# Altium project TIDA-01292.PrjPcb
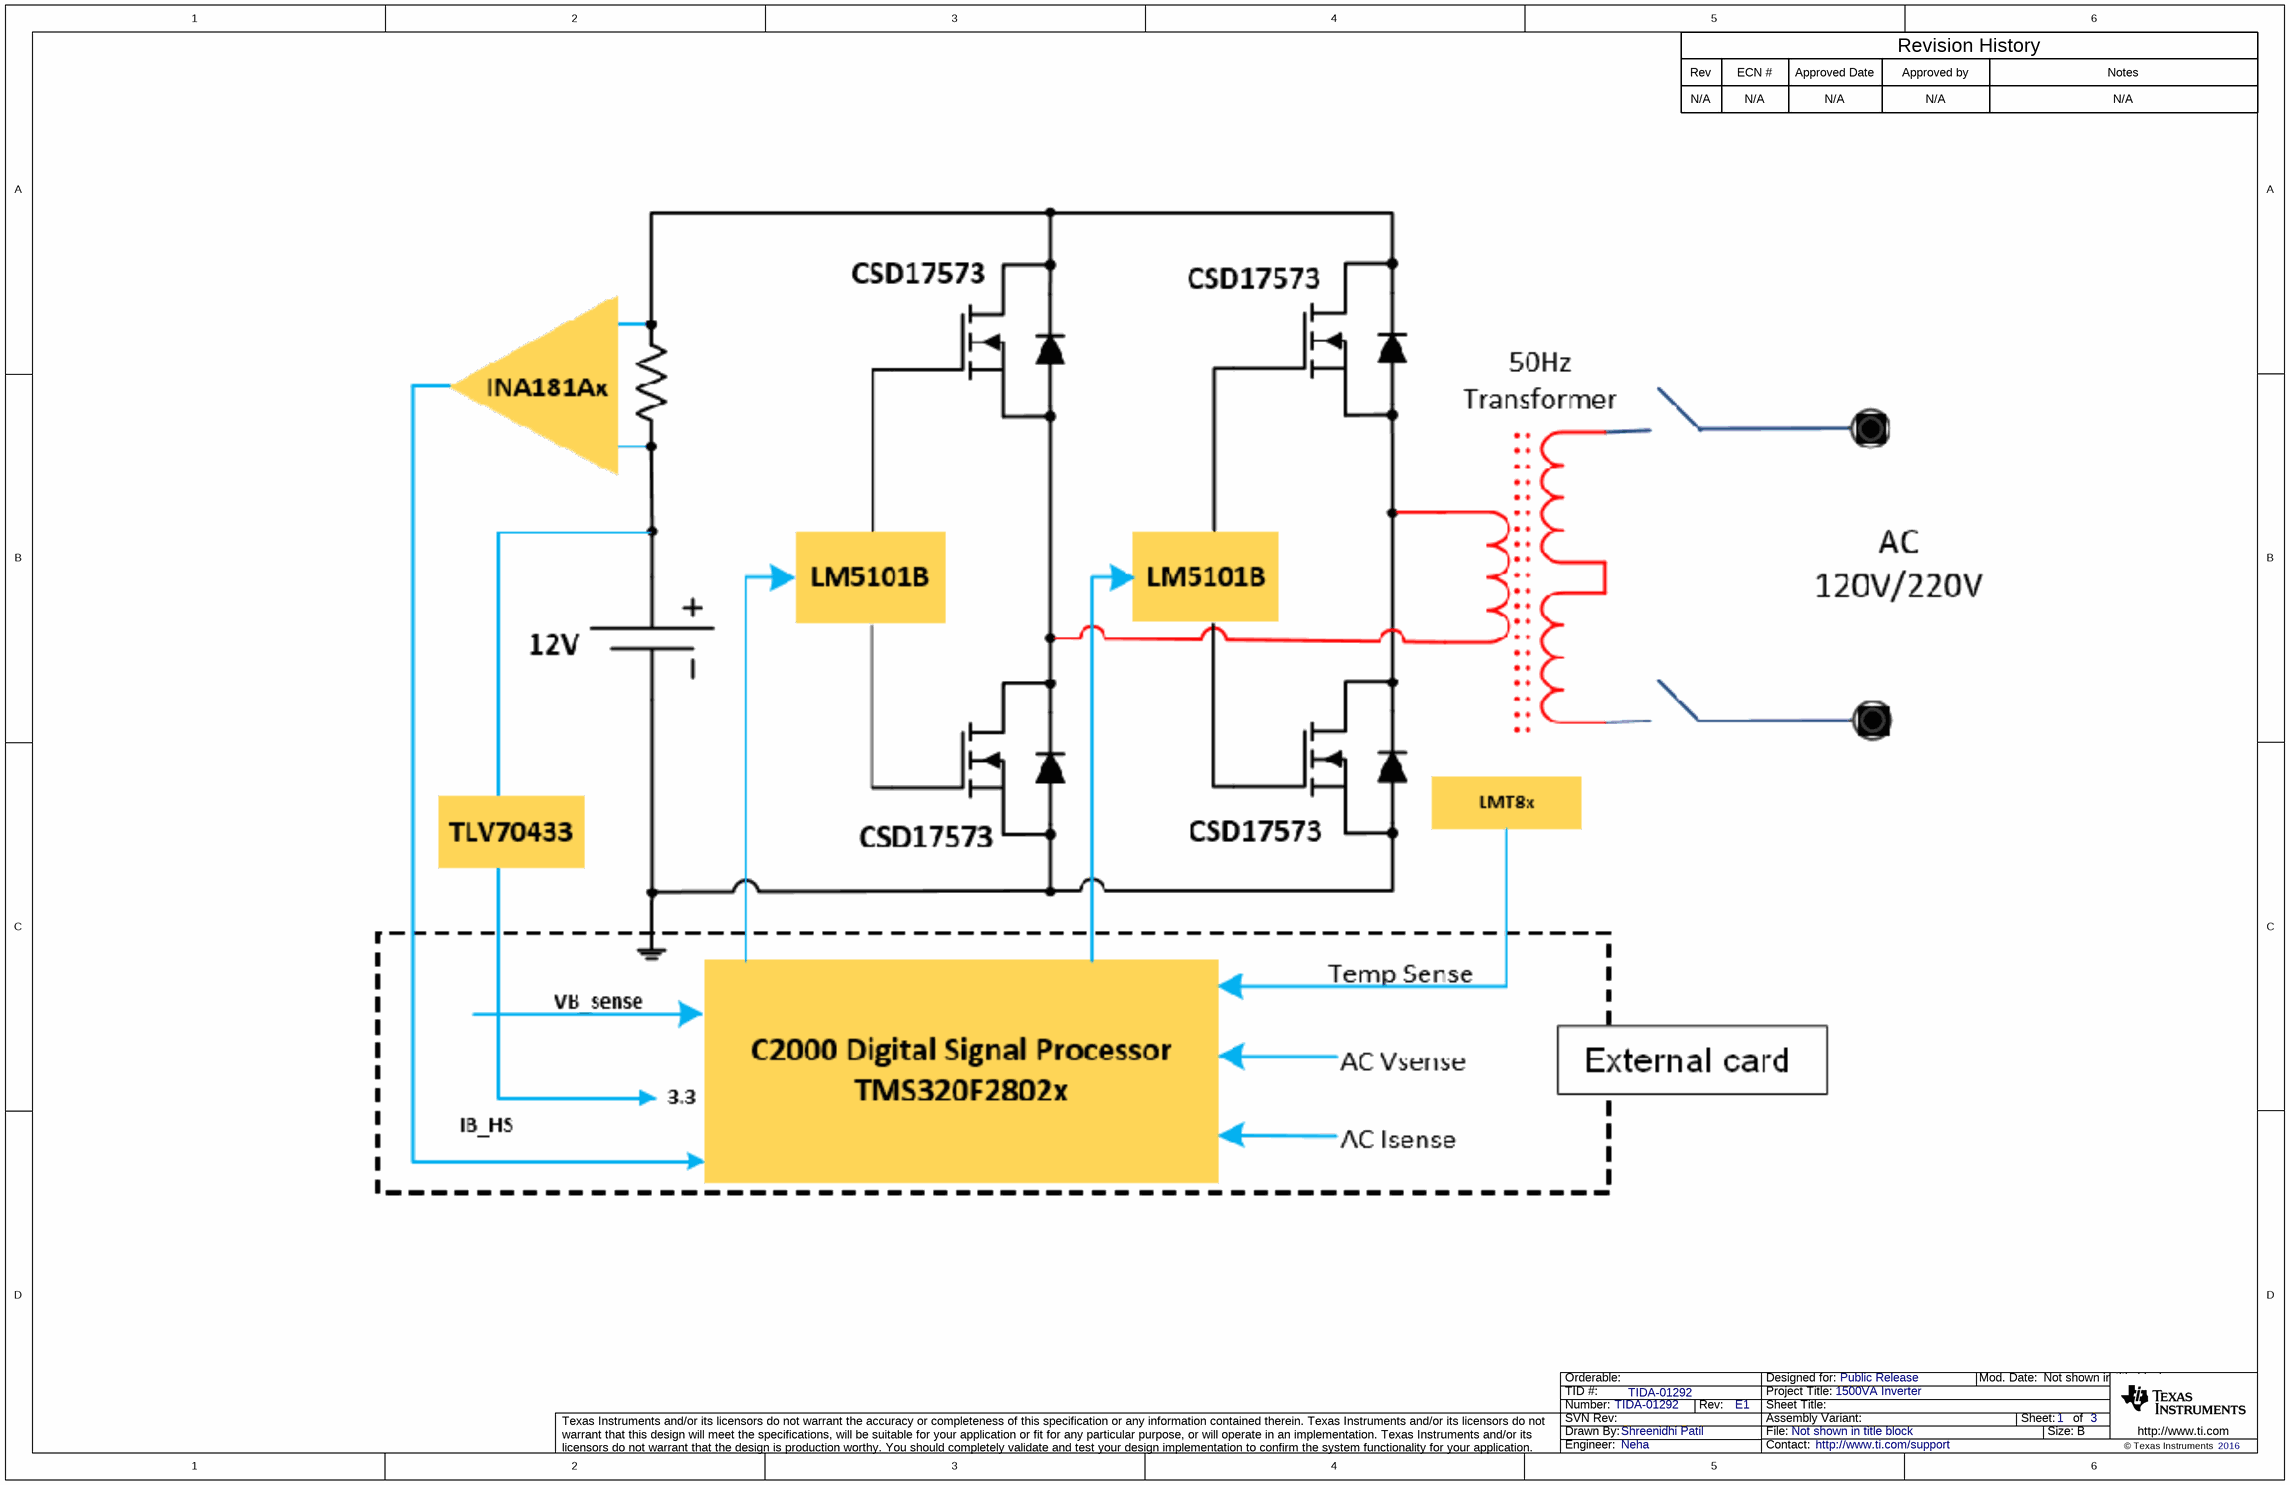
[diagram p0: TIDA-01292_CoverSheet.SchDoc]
CopyrightYear: 2016; PCB_Layout: Manjunath M; PCB_Rev: E1; PRJ_Customer: Public Release; PRJ_Engineer: Neha; PRJ_Number: TIDA-01292; PRJ_Title: 1500VA Inverter; SCH_Rev: E1; TechSupport: http://www.ti.com/support; TID: TIDA-01292
3 sheets, 119 parts. Net scope: global (net labels, ports and power ports of the same name join across sheets).
Board file: TIDA-01292.PcbDoc
Sheets:
  TIDA-01292_CoverSheet.SchDoc
  TIDA-01292_Sheet1.SchDoc
  TIDA-01292_EVM_Hardware.SchDoc

## Sheet TIDA-01292_CoverSheet.SchDoc
size 431 x 279 mm; Date: Not shown in title block; ApprovedBy: Not shown in title block; CheckedBy: Not shown in title block; Author: Not shown in title block; CompanyName: Not shown in title block; DrawnBy: Shreenidhi Patil; Engineer: Not shown in title block; Organization: Not shown in title block; Address1: Not shown in title block; Address2: Not shown in title block; Address3: Not shown in title block; Address4: Not shown in title block; DocumentNumber: 1; Revision: Use project parameter SCH_Rev; SheetNumber: 1; SheetTotal: 3; PageSetup: Record=PageOptions¦CenterHorizontal=True¦CenterVertical=True¦PrintScale=1.00¦XCorrection=1.00¦YCorrection=1.00¦PrintKind=0¦BorderSize=5000000¦LeftOffset=0¦BottomOffset=0¦Orientation=2¦PaperLength=1000¦PaperWidth=1000¦Scale=100¦PaperSource=15¦PrintQuality=600¦MediaType=1¦DitherType=10¦PaperKind=Letter¦PrintScaleMode=1

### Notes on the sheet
- Rev
- N/A
- ECN #
- Approved Date
- Approved by
- Revision History
- Notes

## Sheet TIDA-01292_Sheet1.SchDoc
size 431 x 279 mm; Date: Not shown in title block; ApprovedBy: Not shown in title block; CheckedBy: Not shown in title block; Author: Not shown in title block; CompanyName: Not shown in title block; DrawnBy: Shreenidhi Patil; Engineer: Not shown in title block; Organization: Not shown in title block; Address1: Not shown in title block; Address2: Not shown in title block; Address3: Not shown in title block; Address4: Not shown in title block; DocumentNumber: 1; Revision: Use project parameter SCH_Rev; SheetNumber: 2; SheetTotal: 3; PageSetup: Record=PageOptions¦CenterHorizontal=True¦CenterVertical=True¦PrintScale=1.00¦XCorrection=1.00¦YCorrection=1.00¦PrintKind=0¦BorderSize=5000000¦LeftOffset=0¦BottomOffset=0¦Orientation=2¦PaperLength=1000¦PaperWidth=1000¦Scale=100¦PaperSource=15¦PrintQuality=600¦MediaType=1¦DitherType=10¦PaperKind=Letter¦PrintScaleMode=1
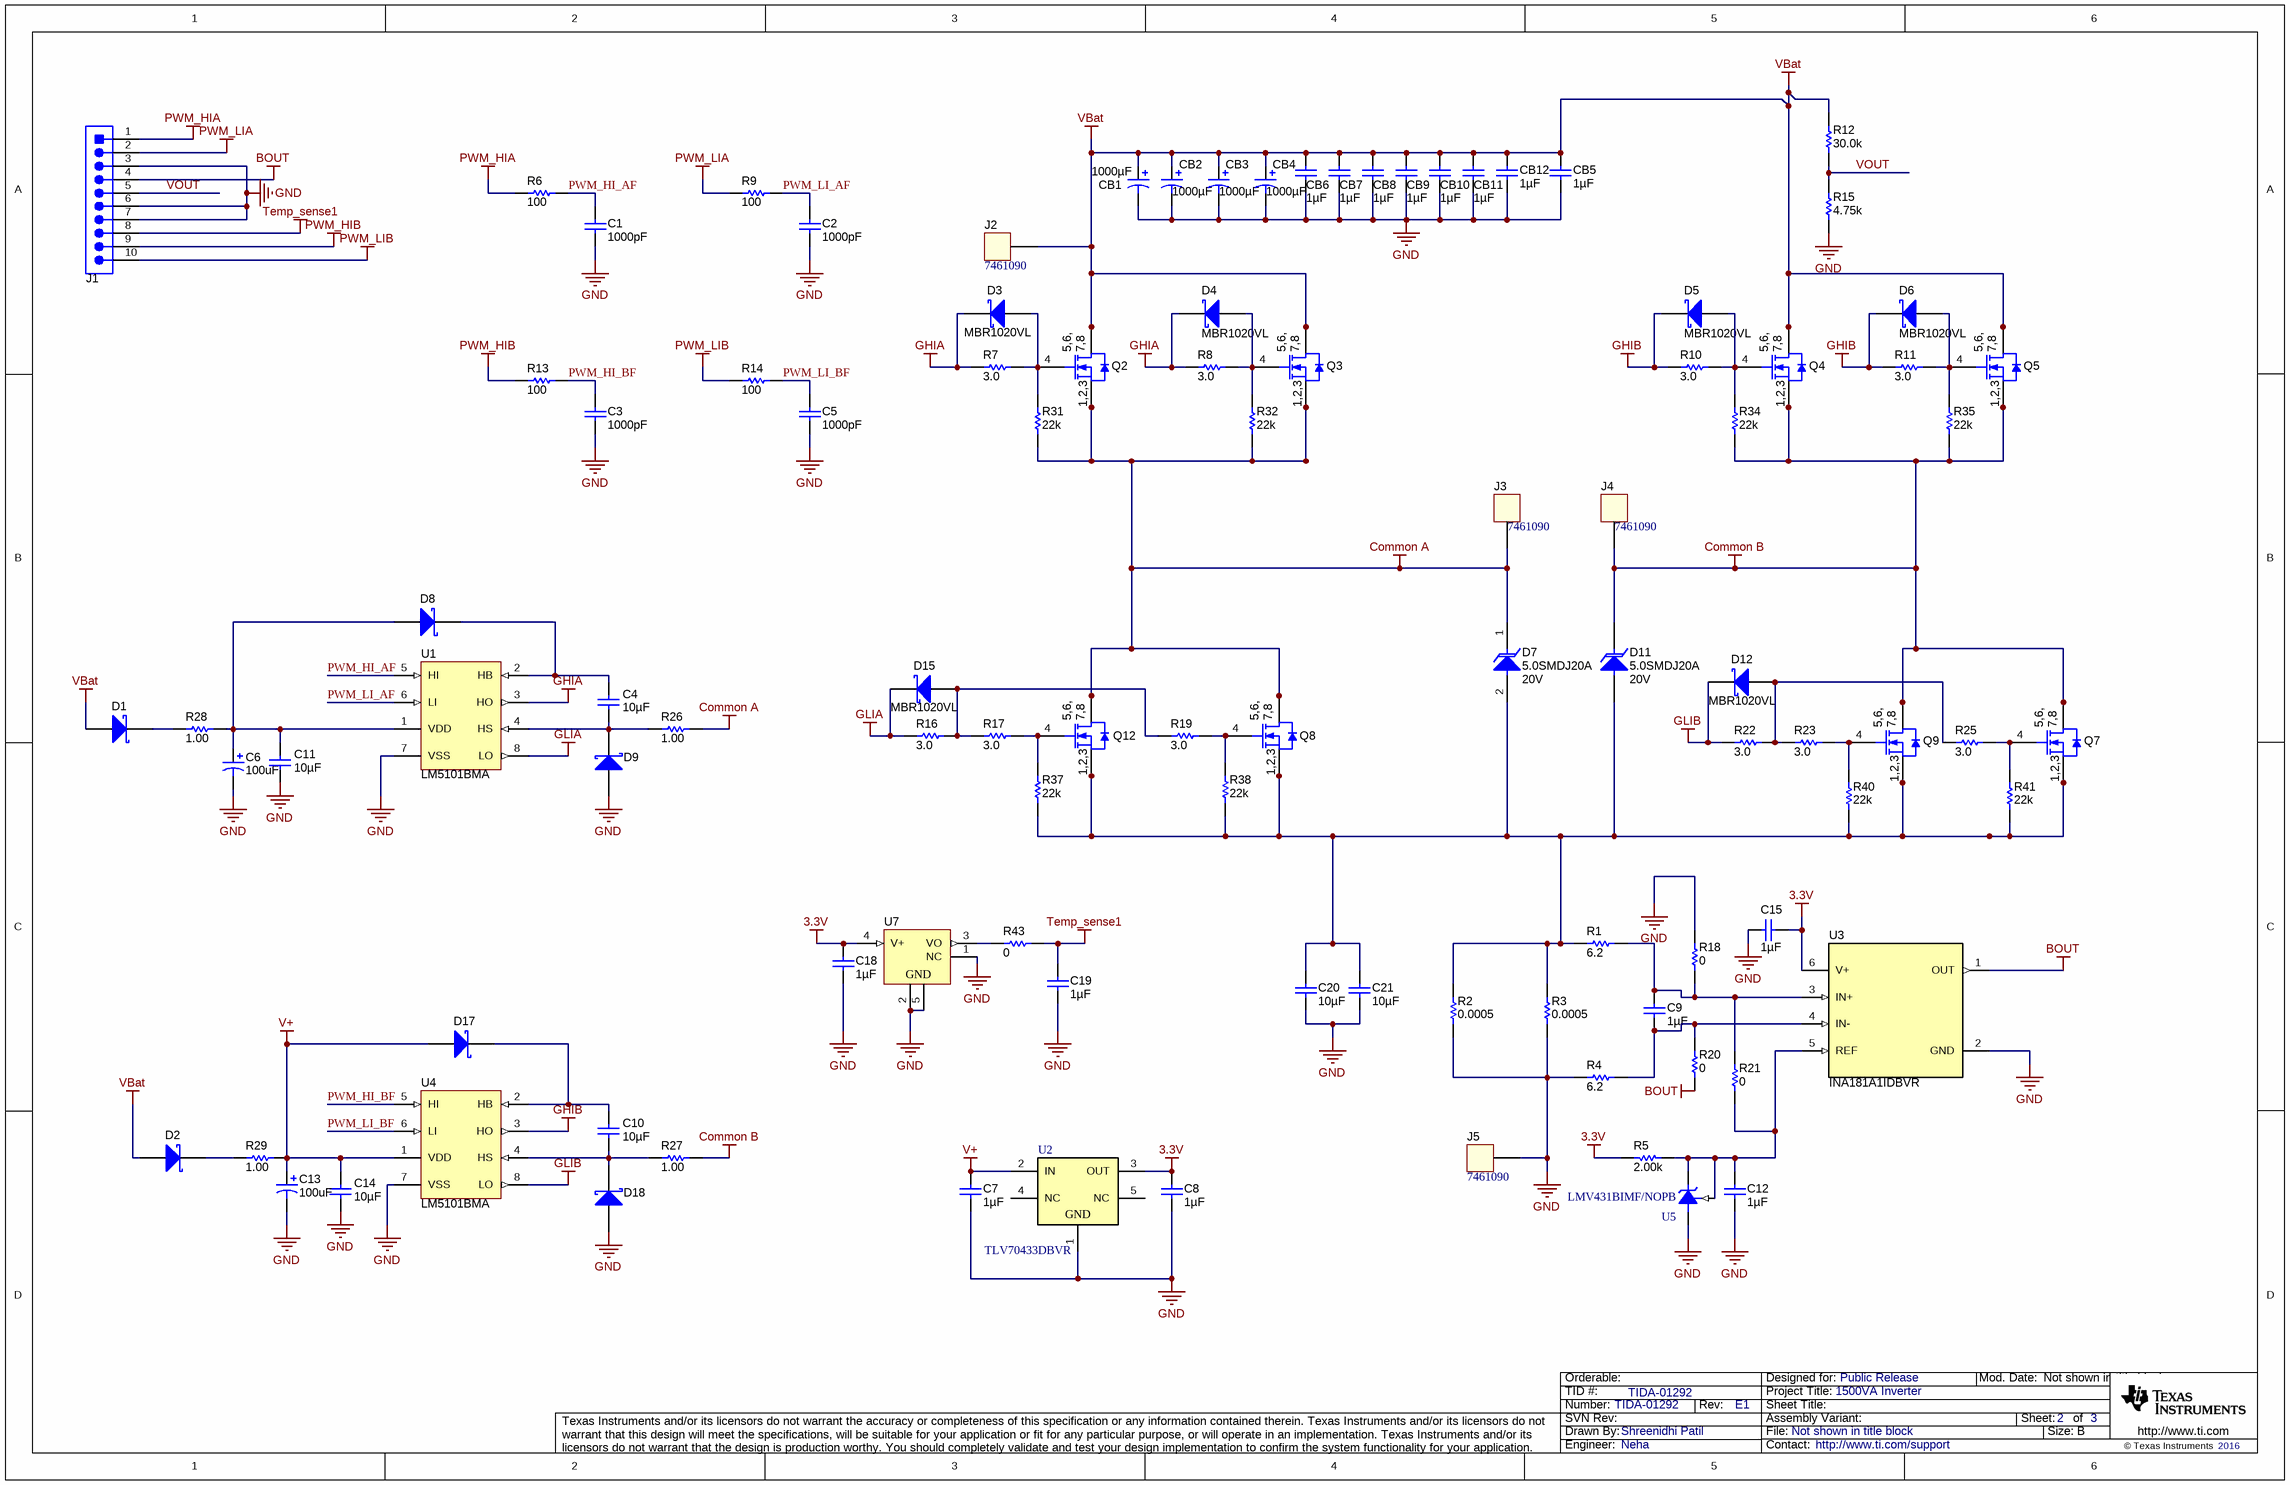
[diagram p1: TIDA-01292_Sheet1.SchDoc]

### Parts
C1  ValueDisplayed: 1000pF  [0603]  (hidden comment: 885012206034)
C2  ValueDisplayed: 1000pF  [0603]  (hidden comment: 885012206034)
C3  ValueDisplayed: 1000pF  [0603]  (hidden comment: 885012206034)
C4  ValueDisplayed: 10µF  [1206_180]  (hidden comment: C3216X5R1H106K160AB)
C5  ValueDisplayed: 1000pF  [0603]  (hidden comment: 885012206034)
C6  ValueDisplayed: 100uF  [ZLH_1000x2300]  (hidden comment: 860130475005)
C7  ValueDisplayed: 1µF  [0603]  (hidden comment: C0603C105K3RACTU)
C8  ValueDisplayed: 1µF  [0603]  (hidden comment: C0603C105K3RACTU)
C9  ValueDisplayed: 1µF  [0603]  (hidden comment: C0603C105K3RACTU)
C10  ValueDisplayed: 10µF  [1206_180]  (hidden comment: C3216X5R1H106K160AB)
C11  ValueDisplayed: 10µF  [1206_180]  (hidden comment: C3216X5R1H106K160AB)
C12  ValueDisplayed: 1µF  [0603]  (hidden comment: C0603C105K3RACTU)
C13  ValueDisplayed: 100uF  [ZLH_1000x2300]  (hidden comment: 860130475005)
C14  ValueDisplayed: 10µF  [1206_180]  (hidden comment: C3216X5R1H106K160AB)
C15  ValueDisplayed: 1µF  [0603]  (hidden comment: C0603C105K3RACTU)
C18  ValueDisplayed: 1µF  [0603]  (hidden comment: C0603C105K3RACTU)
C19  ValueDisplayed: 1µF  [0603]  (hidden comment: C0603C105K3RACTU)
C20  ValueDisplayed: 10µF  [1210_280]  (hidden comment: 1210YD106KAT2A)
C21  ValueDisplayed: 10µF  [1210_280]  (hidden comment: 1210YD106KAT2A)
CB1  ValueDisplayed: 1000µF  [ZLH_1000x2300]  (hidden comment: 25ZLH1000MEFC10X23)
CB2  ValueDisplayed: 1000µF  [ZLH_1000x2300]  (hidden comment: 25ZLH1000MEFC10X23)
CB3  ValueDisplayed: 1000µF  [ZLH_1000x2300]  (hidden comment: 25ZLH1000MEFC10X23)
CB4  ValueDisplayed: 1000µF  [ZLH_1000x2300]  (hidden comment: 25ZLH1000MEFC10X23)
CB5  ValueDisplayed: 1µF  [1206]  (hidden comment: 12063C105KAT2A)
CB6  ValueDisplayed: 1µF  [1206]  (hidden comment: 12063C105KAT2A)
CB7  ValueDisplayed: 1µF  [1206]  (hidden comment: 12063C105KAT2A)
CB8  ValueDisplayed: 1µF  [1206]  (hidden comment: 12063C105KAT2A)
CB9  ValueDisplayed: 1µF  [1206]  (hidden comment: 12063C105KAT2A)
CB10  ValueDisplayed: 1µF  [1206]  (hidden comment: 12063C105KAT2A)
CB11  ValueDisplayed: 1µF  [1206]  (hidden comment: 12063C105KAT2A)
CB12  ValueDisplayed: 1µF  [1206]  (hidden comment: 12063C105KAT2A)
D1  MBR1020VL  [SOD-123F]  (value not drawn)
D2  MBR1020VL  [SOD-123F]  (value not drawn)
D3  MBR1020VL  [SOD-123F]
D4  MBR1020VL  [SOD-123F]
D5  MBR1020VL  [SOD-123F]
D6  MBR1020VL  [SOD-123F]
D7  5.0SMDJ20A  value 20V  [SMC]
D8  MBR1020VL  [SOD-123F]  (value not drawn)
D9  MBR1020VL  [SOD-123F]  (value not drawn)
D11  5.0SMDJ20A  value 20V  [SMC]
D12  MBR1020VL  [SOD-123F]
D15  MBR1020VL  [SOD-123F]
D17  MBR1020VL  [SOD-123F]  (value not drawn)
D18  MBR1020VL  [SOD-123F]  (value not drawn)
J1  TSW-110-07-G-S  [TSW-110-07-G-S]  (value not drawn)
J2  7461090  [7461090_Chemical Surface]
J3  7461090  [7461090_Chemical Surface]
J4  7461090  [7461090_Chemical Surface]
J5  7461090  [7461090_Chemical Surface]
Q2  CSD17573Q5B  [TRANS_NexFET_Q5B]  (value not drawn)
Q3  CSD17573Q5B  [TRANS_NexFET_Q5B]  (value not drawn)
Q4  CSD17573Q5B  [TRANS_NexFET_Q5B]  (value not drawn)
Q5  CSD17573Q5B  [TRANS_NexFET_Q5B]  (value not drawn)
Q7  CSD17573Q5B  [TRANS_NexFET_Q5B]  (value not drawn)
Q8  CSD17573Q5B  [TRANS_NexFET_Q5B]  (value not drawn)
Q9  CSD17573Q5B  [TRANS_NexFET_Q5B]  (value not drawn)
Q12  CSD17573Q5B  [TRANS_NexFET_Q5B]  (value not drawn)
R1  ValueDisplayed: 6.2  [0603]  (hidden comment: CRCW06036R20JNEA)
R2  ValueDisplayed: 0.0005  [CSS2725_0005]  (hidden comment: CSS2725FTL500)
R3  ValueDisplayed: 0.0005  [CSS2725_0005]  (hidden comment: CSS2725FTL500)
R4  ValueDisplayed: 6.2  [0603]  (hidden comment: CRCW06036R20JNEA)
R5  ValueDisplayed: 2.00k  [0603]  (hidden comment: CRCW06032K00FKEA)
R6  ValueDisplayed: 100  [0603]  (hidden comment: CRCW0603100RFKEA)
R7  ValueDisplayed: 3.0  [1206]  (hidden comment: CRCW12063R00JNEA)
R8  ValueDisplayed: 3.0  [1206]  (hidden comment: CRCW12063R00JNEA)
R9  ValueDisplayed: 100  [0603]  (hidden comment: CRCW0603100RFKEA)
R10  ValueDisplayed: 3.0  [1206]  (hidden comment: CRCW12063R00JNEA)
R11  ValueDisplayed: 3.0  [1206]  (hidden comment: CRCW12063R00JNEA)
R12  ValueDisplayed: 30.0k  [0603]  (hidden comment: RC0603FR-0730KL)
R13  ValueDisplayed: 100  [0603]  (hidden comment: CRCW0603100RFKEA)
R14  ValueDisplayed: 100  [0603]  (hidden comment: CRCW0603100RFKEA)
R15  ValueDisplayed: 4.75k  [0603]  (hidden comment: RC0603FR-074K75L)
R16  ValueDisplayed: 3.0  [1206]  (hidden comment: CRCW12063R00JNEA)
R17  ValueDisplayed: 3.0  [1206]  (hidden comment: CRCW12063R00JNEA)
R18  ValueDisplayed: 0  [0603]  (hidden comment: RC0603JR-070RL)
R19  ValueDisplayed: 3.0  [1206]  (hidden comment: CRCW12063R00JNEA)
R20  ValueDisplayed: 0  [0603]  (hidden comment: RC0603JR-070RL)
R21  ValueDisplayed: 0  [0603]  (hidden comment: RC0603JR-070RL)
R22  ValueDisplayed: 3.0  [1206]  (hidden comment: CRCW12063R00JNEA)
R23  ValueDisplayed: 3.0  [1206]  (hidden comment: CRCW12063R00JNEA)
R25  ValueDisplayed: 3.0  [1206]  (hidden comment: CRCW12063R00JNEA)
R26  ValueDisplayed: 1.00  [1206]  (hidden comment: RC1206FR-071RL)
R27  ValueDisplayed: 1.00  [1206]  (hidden comment: RC1206FR-071RL)
R28  ValueDisplayed: 1.00  [1206]  (hidden comment: CSR1206FK1R00)
R29  ValueDisplayed: 1.00  [1206]  (hidden comment: CSR1206FK1R00)
R31  ValueDisplayed: 22k  [0603]  (hidden comment: CRCW060322K0JNEA)
R32  ValueDisplayed: 22k  [0603]  (hidden comment: CRCW060322K0JNEA)
R34  ValueDisplayed: 22k  [0603]  (hidden comment: CRCW060322K0JNEA)
R35  ValueDisplayed: 22k  [0603]  (hidden comment: CRCW060322K0JNEA)
R37  ValueDisplayed: 22k  [0603]  (hidden comment: CRCW060322K0JNEA)
R38  ValueDisplayed: 22k  [0603]  (hidden comment: CRCW060322K0JNEA)
R40  ValueDisplayed: 22k  [0603]  (hidden comment: CRCW060322K0JNEA)
R41  ValueDisplayed: 22k  [0603]  (hidden comment: CRCW060322K0JNEA)
R43  ValueDisplayed: 0  [0603]  (hidden comment: CRCW06030000Z0EA)
U1  LM5101BMA  [M08A_N]
U2  TLV70433DBVR  [DBV0005A_N]
U3  INA181A1IDBVR  [DBV0006A_N]
U4  LM5101BMA  [M08A_N]
U5  LMV431BIMF/NOPB  [MF03A_N]
U7  LM20CIM7X  [MAA05A_N]  (value not drawn)

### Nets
3.3V: C8.1 C15.1 C18.1 R5.2 U2.3(OUT) U3.6(V+) U7.4(V+)
BOUT: J1.4 R20.1 U3.1(OUT)
Common A: D7.1(K) J3.1 Q2.1(S) Q2.2(S) Q2.3(S) Q3.1(S) Q3.2(S) Q3.3(S) Q8.5(D) Q8.6(D) Q8.7(D) Q8.8(D) Q12.5(D) Q12.6(D) Q12.7(D) Q12.8(D) R26.2 R31.1 R32.1
Common B: D11.1(K) J4.1 Q4.1(S) Q4.2(S) Q4.3(S) Q5.1(S) Q5.2(S) Q5.3(S) Q7.5(D) Q7.6(D) Q7.7(D) Q7.8(D) Q9.5(D) Q9.6(D) Q9.7(D) Q9.8(D) R27.2 R34.1 R35.1
GHIA: D3.1(K) D4.1(K) R7.1 R8.1 U1.3(HO)
GHIB: D5.1(K) D6.1(K) R10.1 R11.1 U4.3(HO)
GLIA: D15.1(K) R16.1 U1.8(LO)
GLIB: D12.1(K) R22.1 U4.8(LO)
GND: C1.2 C2.2 C3.2 C5.2 C6.2(-) C7.2 C8.2 C11.2 C12.2 C13.2(-) C14.2 C15.2 C18.2 C19.2 C20.2 C21.2 CB1.2(-) CB2.2(-) CB3.2(-) CB4.2(-) CB5.2 CB6.2 CB7.2 CB8.2 CB9.2 CB10.2 CB11.2 CB12.2 D9.2(A) D18.2(A) J1.3 J1.6 J1.7 J5.1 R2.1 R3.1 R4.1 R15.1 R18.2 U1.7(VSS) U2.1(GND) U3.2(GND) U4.7(VSS) U5.3(A) U7.1(NC) U7.2(GND) U7.5(GND)
PWM_HIA: J1.1 R6.1
PWM_HIB: J1.9 R13.1
PWM_LIA: J1.2 R9.1
PWM_LIB: J1.10 R14.1
Temp_sense1: C19.1 J1.8 R43.2
V+: C7.1 C13.1(+) C14.1 D17.2(A) R29.2 U2.2(IN) U4.1(VDD)
VBat: CB1.1(+) CB2.1(+) CB3.1(+) CB4.1(+) CB5.1 CB6.1 CB7.1 CB8.1 CB9.1 CB10.1 CB11.1 CB12.1 D1.2(A) D2.2(A) J2.1 Q2.5(D) Q2.6(D) Q2.7(D) Q2.8(D) Q3.5(D) Q3.6(D) Q3.7(D) Q3.8(D) Q4.5(D) Q4.6(D) Q4.7(D) Q4.8(D) Q5.5(D) Q5.6(D) Q5.7(D) Q5.8(D) R12.2
PWM_HI_AF: C1.1 R6.2 U1.5(HI)
PWM_HI_BF: C3.1 R13.2 U4.5(HI)
PWM_LI_AF: C2.1 R9.2 U1.6(LI)
PWM_LI_BF: C5.1 R14.2 U4.6(LI)
VOUT: J1.5 R12.1 R15.2
NetC4_1: C4.1 D8.1(K) U1.2(HB)
NetC4_2: C4.2 D9.1(K) R26.1 U1.4(HS)
NetC6_1: C6.1(+) C11.1 D8.2(A) R28.2 U1.1(VDD)
NetC9_1: C9.1 R1.2 R18.1 R21.2 U3.3(IN+)
NetC9_2: C9.2 R4.2 R20.2 U3.4(IN-)
NetC10_1: C10.1 D17.1(K) U4.2(HB)
NetC10_2: C10.2 D18.1(K) R27.1 U4.4(HS)
NetC12_1: C12.1 R5.1 R21.1 U3.5(REF) U5.1(REF) U5.2(K)
NetC20_1: C20.1 C21.1 D7.2(A) D11.2(A) Q7.1(S) Q7.2(S) Q7.3(S) Q8.1(S) Q8.2(S) Q8.3(S) Q9.1(S) Q9.2(S) Q9.3(S) Q12.1(S) Q12.2(S) Q12.3(S) R1.1 R2.2 R3.2 R37.1 R38.1 R40.1 R41.1
NetD1_1: D1.1(K) R28.1
NetD2_1: D2.1(K) R29.1
NetD3_2: D3.2(A) Q2.4(G) R7.2 R31.2
NetD4_2: D4.2(A) Q3.4(G) R8.2 R32.2
NetD5_2: D5.2(A) Q4.4(G) R10.2 R34.2
NetD6_2: D6.2(A) Q5.4(G) R11.2 R35.2
NetD12_2: D12.2(A) R22.2 R23.1 R25.1
NetD15_2: D15.2(A) R16.2 R17.1 R19.1
NetQ7_4: Q7.4(G) R25.2 R41.2
NetQ8_4: Q8.4(G) R19.2 R38.2
NetQ9_4: Q9.4(G) R23.2 R40.2
NetQ12_4: Q12.4(G) R17.2 R37.2
NetR43_1: R43.1 U7.3(VO)

Not connected (* = marked no-connect by the designer): U2 4(NC) 5(NC)

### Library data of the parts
C1-C3 C5 = 885012206034: CAP, CERM, 1000 pF, 16 V, +/- 10%, X7R, 0603; Manufacturer: Wurth Elektronik; Polarized: N; CompType: Capacitor; Value: 1000pF; U/M: EA; Cap_F: 0.000000001; Tolerance_%: 10; Value1: Unknown; VDC_V: 16; Value2: 16V; TaMin_C: -55; TaMax_C: 125; SizeArea_mm2: 1.28; SizeAreaWB_mm2: 4.68; SizeX_mm: 1.6; SizeY_mm: 0.8; SizeZ_mm: 1; AEC Category: Q200
C4 C10 C11 C14 = C3216X5R1H106K160AB: CAP, CERM, 10 µF, 50 V, +/- 10%, X5R, 1206; Manufacturer: TDK; Polarized: N; CompType: Capacitor; Value: 10uF; U/M: EA; Cap_F: 0.00001; Tolerance_%: 10; Value1: 0.002229 ohm; VDC_V: 50; Value2: 50V; ESR_ohm: 0.002229; IRMS_A: 4.85932; TaMin_C: -55; TaMax_C: 85; SizeAreaWB_mm2: 10.92; SizeArea_mm2: 5.12; SizeX_mm: 3.2; SizeY_mm: 1.6; SizeZ_mm: 1.8; AEC Category: Q200
C6 C13 = 25ZLH1000MEFC10X23: CAP ALUM 100UF 20% 25V RADIAL; Manufacturer: Rubycon; Polarized: Y; CompType: Capacitor; U/M: EA; Cap_F: 0.001; Tolerance_%: 20; Value1: 0.018 ohm; VDC_V: 25; ESR_ohm: 0.018; IRMS_A: 2.25; TaMin_C: -40; TaMax_C: 105; Cap_Case: 10x23mm; AEC Category: Q200
C7-C9 C12 C15 C18 C19 = C0603C105K3RACTU: CAP, CERM, 1 µF, 25 V, +/- 10%, X7R, 0603; Manufacturer: Kemet; Polarized: N; CompType: Capacitor; Value: 1uF; U/M: EA; Cap_F: 0.000001; Tolerance_%: 10; Value1: Unknown; VDC_V: 25; Value2: 25V; TaMin_C: -55; TaMax_C: 125; SizeArea_mm2: 1.28; SizeAreaWB_mm2: 4.68; SizeX_mm: 1.6; SizeY_mm: 0.8; SizeZ_mm: 1; AEC Category: Q200
C20 C21 = 1210YD106KAT2A: CAP, CERM, 10 µF, 16 V, +/- 10%, X5R, 1210; Manufacturer: AVX; Polarized: N; CompType: Capacitor; Value: 10uF; U/M: EA; Cap_F: 0.00001; Tolerance_%: 10; Value1: Unknown; VDC_V: 16; Value2: 16V; TaMin_C: -55; TaMax_C: 85; Cap_Case: 1210; SizeArea_mm2: 8; SizeAreaWB_mm2: 14.7; SizeX_mm: 3.2; SizeY_mm: 2.5; SizeZ_mm: 2.8; AEC Category: Q200
CB1-CB4 = 25ZLH1000MEFC10X23: CAP, AL, 1000 µF, 25 V, +/- 20%, 0.018 ohm, TH; Manufacturer: Rubycon; Polarized: Y; CompType: Capacitor; Value: 1000uF; U/M: EA; Cap_F: 0.001; Tolerance_%: 20; VDC_V: 25; Value2: 25V; ESR_ohm: 0.018; IRMS_A: 2.25; TaMin_C: -40; TaMax_C: 105; Cap_Case: 10x23mm; AEC Category: Q200
CB5-CB12 = 12063C105KAT2A: CAP, CERM, 1 µF, 25 V, +/- 10%, X7R, 1206; Manufacturer: AVX; Polarized: N; CompType: Capacitor; Value: 1uF; U/M: EA; Cap_F: 0.000001; Tolerance_%: 10; ESR_ohm: 0.013; Value1: 0.013 ohm; VDC_V: 25; Value2: 25V; TaMin_C: -55; TaMax_C: 125; SizeArea_mm2: 5.12; SizeAreaWB_mm2: 10.92; SizeX_mm: 3.2; SizeY_mm: 1.6; SizeZ_mm: 1.35; AEC Category: Q200
D1-D6 D8 D9 D12 D15 D17 D18 = MBR1020VL: Diode, Schottky, 20 V, 1 A, SOD-123F; Manufacturer: Fairchild Semiconductor; U/M: EA; Vf_V: 0.34; Value: 20V; Value1: 1A; Value2: 0.34V; Io_A: 1; Vr_V: 20; TJmax_C: 125; SizeAreaWB_mm2: 11.7; SizeArea_mm2: 5.6; SizeX_mm: 3.5; SizeY_mm: 1.6; SizeZ_mm: 1.1; AEC Category: Q101; AEC Qualified: N
D7 D11 = 5.0SMDJ20A: Diode, TVS, Uni, 20 V, 5000 W, SMC; Manufacturer: Littelfuse; U/M: EA; Power_W: 6.5; Vr_V: 20; Value1: 6.5W; RJA_CperW: 75; SizeAreaWB_mm2: 83.2686; SizeArea_mm2: 50.5686; SizeX_mm: 8.13; SizeY_mm: 6.22; SizeZ_mm: 2.6; AEC Category: Q101
J1 = TSW-110-07-G-S: Header, 100mil, 10x1, Gold, TH; Manufacturer: Samtec; SymbolCreator: a0412235; Pitch_mm: 2.54; Gender: Male; Shrouded: N; Row_Count: 1; Current_A: 6.3; Voltage_V: 550; Cert_CSA: Y
J2-J5 = 7461090: REDCUBE PRESS-FIT with internal thread, circumference WP-BUCF, M8, 13.5 mm; Pin Number: 20; Rated Current: 340 A; Thread Length: 13.5 mm
Q2-Q5 Q7-Q9 Q12 = CSD17573Q5B: MOSFET, N-CH, 30 V, 100 A, SON 5x6mm; Manufacturer: Texas Instruments; Alternate Manufacturer: None; U/M: EA; ChType: N; Value: 30V; VdsMax_V: 30; Value1: 0.00145 ohm; Rdson45_ohm: 0.00145; Value2: 49 nC; QgTyp_nC: 49; Vgs_V: 20; IdsMax_A: 100; SizeAreaWB_mm2: 57.51; SizeArea_mm2: 31.11; SizeX_mm: 6.1; SizeY_mm: 5.1; SizeZ_mm: 1.05; AEC Category: Q101
R1 R4 = CRCW06036R20JNEA: RES, 6.2, 5%, 0.1 W, 0603; Manufacturer: Vishay-Dale; CompType: Resistor; Value: 6.2; Value_Code: 6R20; Tolerance_%: 5; Power_W: 0.1; Value2: 0.1W; VDC_V: 75; TempCo: 200 ppm/C; EIA_Code: E24; U/M: EA; AEC Category: Q200
R2 R3 = CSS2725FTL500: RES, 0.0005, 1%, 4 W, RES_2725; Manufacturer: Stackpole Electronics Inc; CompType: Resistor; Value: 0.0005; Value_Code: L5000; Tolerance_%: 1; Power_W: 4; Value2: 4W; TempCo: 50 ppm/C; U/M: EA; AEC Category: Q200
R5 = CRCW06032K00FKEA: RES, 2.00 k, 1%, 0.1 W, 0603; Manufacturer: Vishay-Dale; CompType: Resistor; Value: 2.00k; Res_ohm: 2000; Value_Code: 2k00; Tolerance_%: 1; Power_W: 0.1; Value2: 0.1W; VDC_V: 75; TempCo: 100 ppm/C; SizeArea_mm2: 1.28; SizeX_mm: 1.6; SizeY_mm: 0.8; EIA_Code: E96; U/M: EA; AEC Category: Q200
R6 R9 R13 R14 = CRCW0603100RFKEA: RES, 100, 1%, 0.1 W, 0603; Manufacturer: Vishay-Dale; CompType: Resistor; Value: 100; Value_Code: 100R; Tolerance_%: 1; Power_W: 0.1; Value2: 0.1W; VDC_V: 75; TempCo: 100 ppm/C; SizeArea_mm2: 1.28; SizeX_mm: 1.6; SizeY_mm: 0.8; EIA_Code: E96; U/M: EA; AEC Category: Q200
R7 R8 R10 R11 R16 R17 R19 R22 R23 R25 = CRCW12063R00JNEA: RES, 3.0, 5%, 0.25 W, 1206; Manufacturer: Vishay-Dale; CompType: Resistor; Value: 3.0; Res_ohm: 3; Value_Code: 3R00; Tolerance_%: 5; Power_W: 0.25; Value2: 0.25W; VDC_V: 200; TempCo: 200 ppm/C; SizeArea_mm2: 5.12; SizeX_mm: 3.2; SizeY_mm: 1.6; SizeZ_mm: 1.35; EIA_Code: E24; U/M: EA; AEC Category: Q200
R12 = RC0603FR-0730KL: RES, 30.0 k, 1%, 0.1 W, 0603; Manufacturer: Yageo America; CompType: Resistor; Value: 30.0k; Res_ohm: 30000; Value_Code: 30k0; Tolerance_%: 1; Power_W: 0.1; Value2: 0.1W; VDC_V: 150; TempCo: 200 ppm/C; U/M: EA; AEC Category: Q200
R15 = RC0603FR-074K75L: RES, 4.75 k, 1%, 0.1 W, 0603; Manufacturer: Yageo America; CompType: Resistor; Value: 4.75k; Res_ohm: 4750; Value_Code: 4k75; Tolerance_%: 1; Power_W: 0.1; Value2: 0.1W; VDC_V: 150; TempCo: 200 ppm/C; EIA_Code: E96; U/M: EA; AEC Category: Q200
R18 R20 R21 = RC0603JR-070RL: RES, 0, 5%, 0.1 W, 0603; Manufacturer: Yageo America; CompType: Resistor; Value: 0; Value_Code: 0000; Tolerance_%: 5; Power_W: 0.1; Value2: 0.1W; VDC_V: 50; TempCo: 200 ppm/C; SizeArea_mm2: 1.28; SizeX_mm: 1.6; SizeY_mm: 0.8; SizeZ_mm: 1; EIA_Code: E24; U/M: EA; AEC Category: Q200
R26 R27 = RC1206FR-071RL: RES, 1.00, 1%, 0.25 W, 1206; Manufacturer: Yageo America; CompType: Resistor; Value: 1.00; Res_ohm: 1; Value_Code: 1R00; Power_W: 0.25; Value2: 0.25W; VDC_V: 200; TempCo: 200 ppm/C; EIA_Code: E96; U/M: EA; AEC Category: Q200
R28 R29 = CSR1206FK1R00: RES, 1.00, 1%, 0.5 W, 1206; Manufacturer: Stackpole Electronics Inc; CompType: Resistor; Value: 1.00; Res_ohm: 1; Value_Code: 1R00; Power_W: 0.5; Value2: 0.5W; TempCo: 100 ppm/C; SizeArea_mm2: 5.12; SizeX_mm: 3.2; SizeY_mm: 1.6; SizeZ_mm: 1.35; EIA_Code: E96; U/M: EA; AEC Category: Q200
R31 R32 R34 R35 R37 R38 R40 R41 = CRCW060322K0JNEA: RES, 22 k, 5%, 0.1 W, 0603; Manufacturer: Vishay-Dale; CompType: Resistor; Value: 22k; Res_ohm: 22000; Value_Code: 22k0; Tolerance_%: 5; Power_W: 0.1; Value2: 0.1W; VDC_V: 75; TempCo: 200 ppm/C; SizeArea_mm2: 1.28; SizeX_mm: 1.6; SizeY_mm: 0.8; SizeZ_mm: 1; EIA_Code: E24; U/M: EA; AEC Category: Q200
R43 = CRCW06030000Z0EA: RES, 0, 5%, 0.1 W, 0603; Manufacturer: Vishay-Dale; CompType: Resistor; Value: 0; Value_Code: 0000; Tolerance_%: 5; Power_W: 0.1; Value2: 0.1W; VDC_V: 75; TempCo: 200 ppm/C; SizeArea_mm2: 1.28; SizeX_mm: 1.6; SizeY_mm: 0.8; SizeZ_mm: 1; EIA_Code: E24; U/M: EA; AEC Category: Q200
U1 U4 = LM5101BMA: 2A High Voltage High-Side and Low-Side Gate Driver, 8-pin Narrow SOIC; Manufacturer: Texas Instruments; PackageTopMarking: NSZXTT*L5101*BMA; PowerWise: N; CompType: MiscPower
U2 = TLV70433DBVR: Single Output LDO, 150 mA, Fixed 3.3 V Output, 2.5 to 24 V Input, with Ultra-Low IQ, 5-pin SOT-23 (DBV), -40 to 125 degC, Green (RoHS & no Sb/Br); Manufacturer: Texas Instruments; Alternate PartNumber: Equivalent; Accuracy(%): 2; Fixed Output Options(V): 3.3; Iout(Max)(A): 0.15; Iq(Typ)(mA): 0.003; SubFamily: Single Channel LDO; Vdo(Typ)(mV): 400; Vin(Max)(V): 24; Vin(Min)(V): 2.5
U3 = INA181A1IDBVR: Bidirectional, Low- and High-Side Measurement, Multichannel, Voltage Output, Current-Sense Amplifier, DBV0006A (SOT-23-6); Alternate PartNumber: INA181A1IDBVT; Manufacturer: Texas Instruments; SymbolCreator: a0411947; SizeArea_mm2: 8.12; SizeAreaWB_mm2: 14.82; SizeX_mm: 2.8; SizeY_mm: 2.9; SizeZ_mm: 1.45; CompType: IC; U/M: EA
U5 = LMV431BIMF/NOPB: Low-Voltage (1.24V) Adjustable Precision Shunt Regulators, 3-pin SOT-23, Pb-Free; Manufacturer: Texas Instruments; PackageTopMarking: RLB*XTT; PowerWise: N; CompType: MiscPower
U7 = LM20CIM7X: Temperature Sensor Analog, Local -55°C ~ 130°C 11.77mV/°C SC-70-5; PartNumber: LMT88DCKT; Manufacturer: Texas Instruments; PackageTopMarking: T2C*XTT; PowerWise: N; CompType: Temp Sensor IC

## Sheet TIDA-01292_EVM_Hardware.SchDoc
size 431 x 279 mm; Date: Not shown in title block; ApprovedBy: Not shown in title block; CheckedBy: Not shown in title block; Author: Not shown in title block; CompanyName: Not shown in title block; DrawnBy: Shreenidhi Patil; Engineer: Not shown in title block; Organization: Not shown in title block; Address1: Not shown in title block; Address2: Not shown in title block; Address3: Not shown in title block; Address4: Not shown in title block; DocumentNumber: 1; Revision: Use project parameter SCH_Rev; SheetNumber: 3; SheetTotal: 3; PageSetup: Record=PageOptions¦CenterHorizontal=True¦CenterVertical=True¦PrintScale=1.00¦XCorrection=1.00¦YCorrection=1.00¦PrintKind=0¦BorderSize=5000000¦LeftOffset=0¦BottomOffset=0¦Orientation=2¦PaperLength=1000¦PaperWidth=1000¦Scale=100¦PaperSource=15¦PrintQuality=600¦MediaType=1¦DitherType=10¦PaperKind=Letter¦PrintScaleMode=1
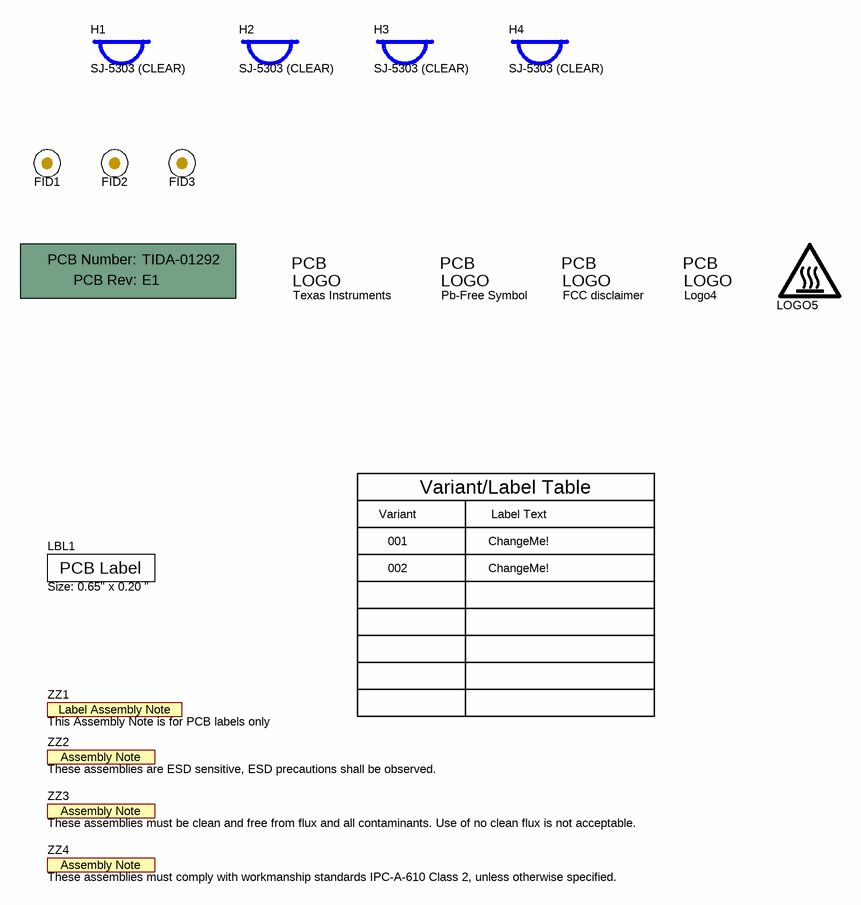
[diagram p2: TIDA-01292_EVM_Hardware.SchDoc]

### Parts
!PCB1  Printed Circuit Board  (value not drawn)  (mechanical)
FID1  Fiducial  [Fiducial10-20]  (value not drawn)
FID2  Fiducial  [Fiducial10-20]  (value not drawn)
FID3  Fiducial  [Fiducial10-20]  (value not drawn)
H1  SJ-5303 (CLEAR)  [Bumpon_SJ5003Transparent]
H2  SJ-5303 (CLEAR)  [Bumpon_SJ5003Transparent]
H3  SJ-5303 (CLEAR)  [Bumpon_SJ5003Transparent]
H4  SJ-5303 (CLEAR)  [Bumpon_SJ5003Transparent]
LBL1  Size: 0.65" x 0.20 "  [Label_650x200]
Logo1  Texas Instruments  [TI_Stacked_Overlay_Small]  (no BOM)
Logo2  Pb-Free Symbol  [Pb-Free_Overlay_Small]  (no BOM)
Logo3  FCC disclaimer  [FCC_disclaimer]  (no BOM)
Logo4  ESD Susceptible  [ESD_Overlay_Medium]  (value not drawn)  (no BOM)
LOGO5  CAUTION HOT SURFACE  [IEC_HotSurface_Small]  (value not drawn)  (no BOM)
ZZ1  This Assembly Note is for PCB labels only  [AssemblyNoteLabel]  (no BOM)
ZZ2  These assemblies are ESD sensitive, ESD precautions shall be observed.  [AssemblyNote]  (no BOM)
ZZ3  These assemblies must be clean and free from flux and all contaminants. Use of no clean flux is not acceptable.  [AssemblyNote]  (no BOM)
ZZ4  These assemblies must comply with workmanship standards IPC-A-610 Class 2, unless otherwise specified.  [AssemblyNote]  (no BOM)

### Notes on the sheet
- Variant
- Variant/Label Table
- Label Text
- 001
- 002
- ChangeMe!

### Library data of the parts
!PCB1 = PCB: Manufacturer: Any; PartNumber: TIDA-01292; SymbolCreator: a0412235
FID1-FID3 = Fiducial: Fiducial mark.  There is nothing to buy or mount.; SymbolCreator: codlsc
H1-H4 = SJ-5303 (CLEAR): Bumpon, Hemisphere, 0.44 X 0.20, Clear; Manufacturer: 3M; SymbolCreator: a0412235
LBL1 = THT-14-423-10: Thermal Transfer Printable Labels, 0.650" W x 0.200" H - 10,000 per roll; Manufacturer: Brady; SymbolCreator: a0412235; CompType: Label
Logo1 = TI_Logo: Texas Instrument Corporate Signature; SymbolCreator: codlsc
Logo2 = Pb-Free: SymbolCreator: a0412235
Logo3 = FCC_disclaimer: SymbolCreator: codlsc
Logo4 = ESD_Susceptible: ESD Susceptible Symbol; SymbolCreator: a0412235
LOGO5 = IEC_HotSurface: IEC 61010-1 Hot Surface Warning; SymbolCreator: a0412235
ZZ1 = AssemblyNoteLabel: SymbolCreator: a0412235
ZZ2-ZZ4 = AssemblyNote: SymbolCreator: codlsc

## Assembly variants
001: not fitted C5 FID1 FID2 FID3 R18 R20 R21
